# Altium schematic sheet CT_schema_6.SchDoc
size 368 x 245 mm
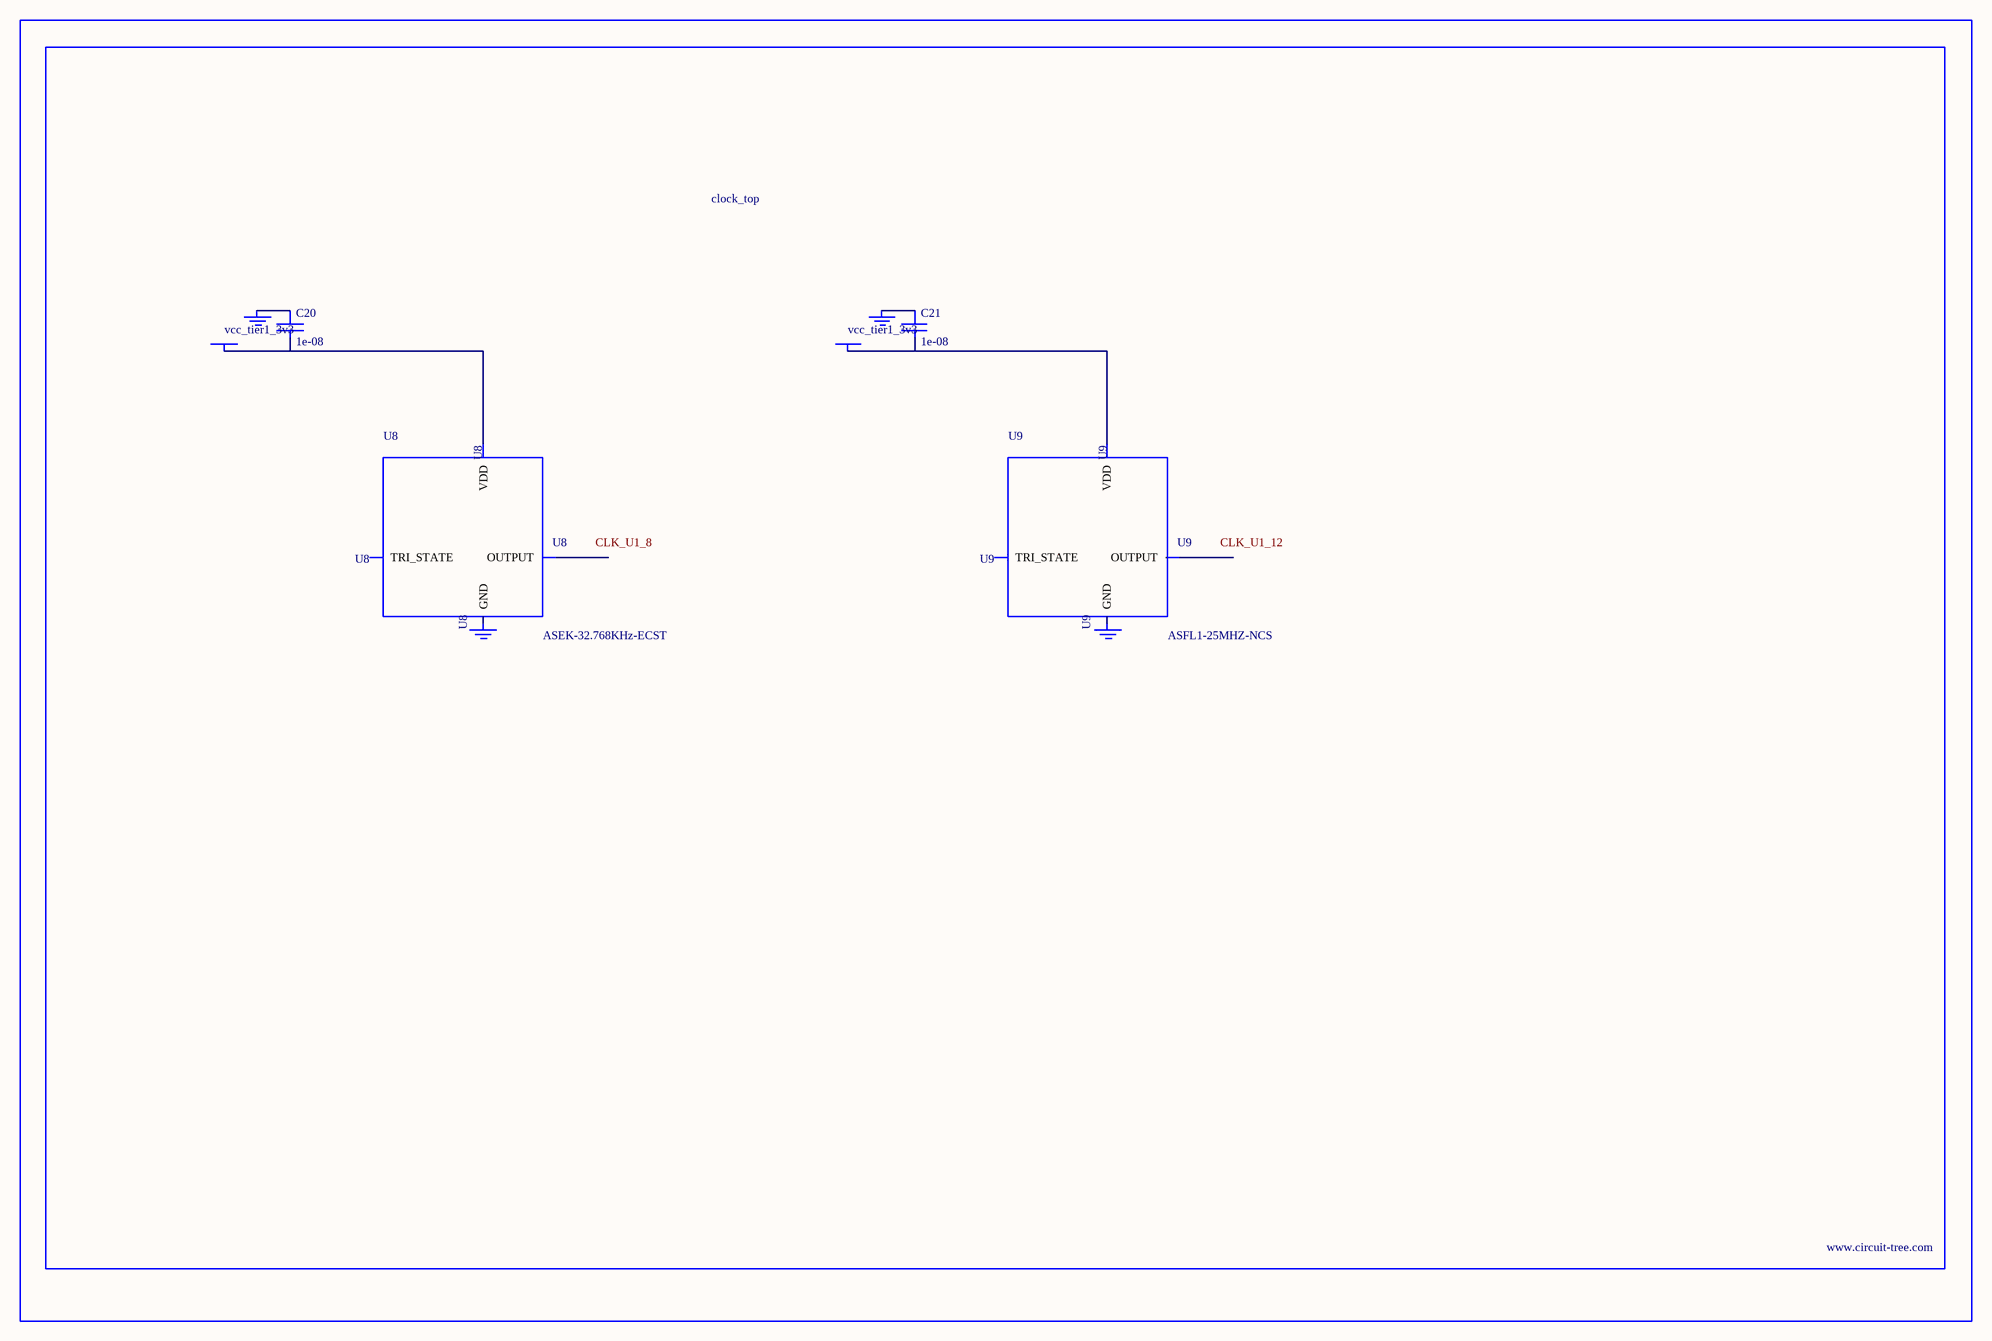
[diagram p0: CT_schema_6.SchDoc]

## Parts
BORDER5  (no value)
C20  1e-08  [C0402]
C21  1e-08  [C0402]
GND_INSTANCE_5_0  (no value)
GND_INSTANCE_5_1  (no value)
GND_INSTANCE_5_2  (no value)
GND_INSTANCE_5_3  (no value)
POWER_INSTANCE_5_0  vcc_tier1_3v3
POWER_INSTANCE_5_1  vcc_tier1_3v3
U8  ASEK-32.768KHz-ECST  [ASEK]
U9  ASFL1-25MHZ-NCS  [ASFL1]

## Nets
NetC20_1: C20.1 GND_INSTANCE_5_0.0(GND)
NetC20_2: C20.2 POWER_INSTANCE_5_0.0(PWR) U8.4(VDD)
NetC21_1: C21.1 GND_INSTANCE_5_2.0(GND)
NetC21_2: C21.2 POWER_INSTANCE_5_1.0(PWR) U9.4(VDD)

Not connected (* = marked no-connect by the designer): GND_INSTANCE_5_1 0(GND); GND_INSTANCE_5_3 0(GND); U8 1(TRI_STATE) 2(GND) 3(OUTPUT); U9 1(TRI_STATE) 2(GND) 3(OUTPUT)

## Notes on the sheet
- Labels drawn without touching a wire or pin: CLK_U1_8, CLK_U1_12

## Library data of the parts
BORDER5 = BORDER_PAGE5
C20 C21 = C0402C103K3RAC
GND_INSTANCE_5_0-GND_INSTANCE_5_3 = GND
POWER_INSTANCE_5_0 POWER_INSTANCE_5_1 = PWR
